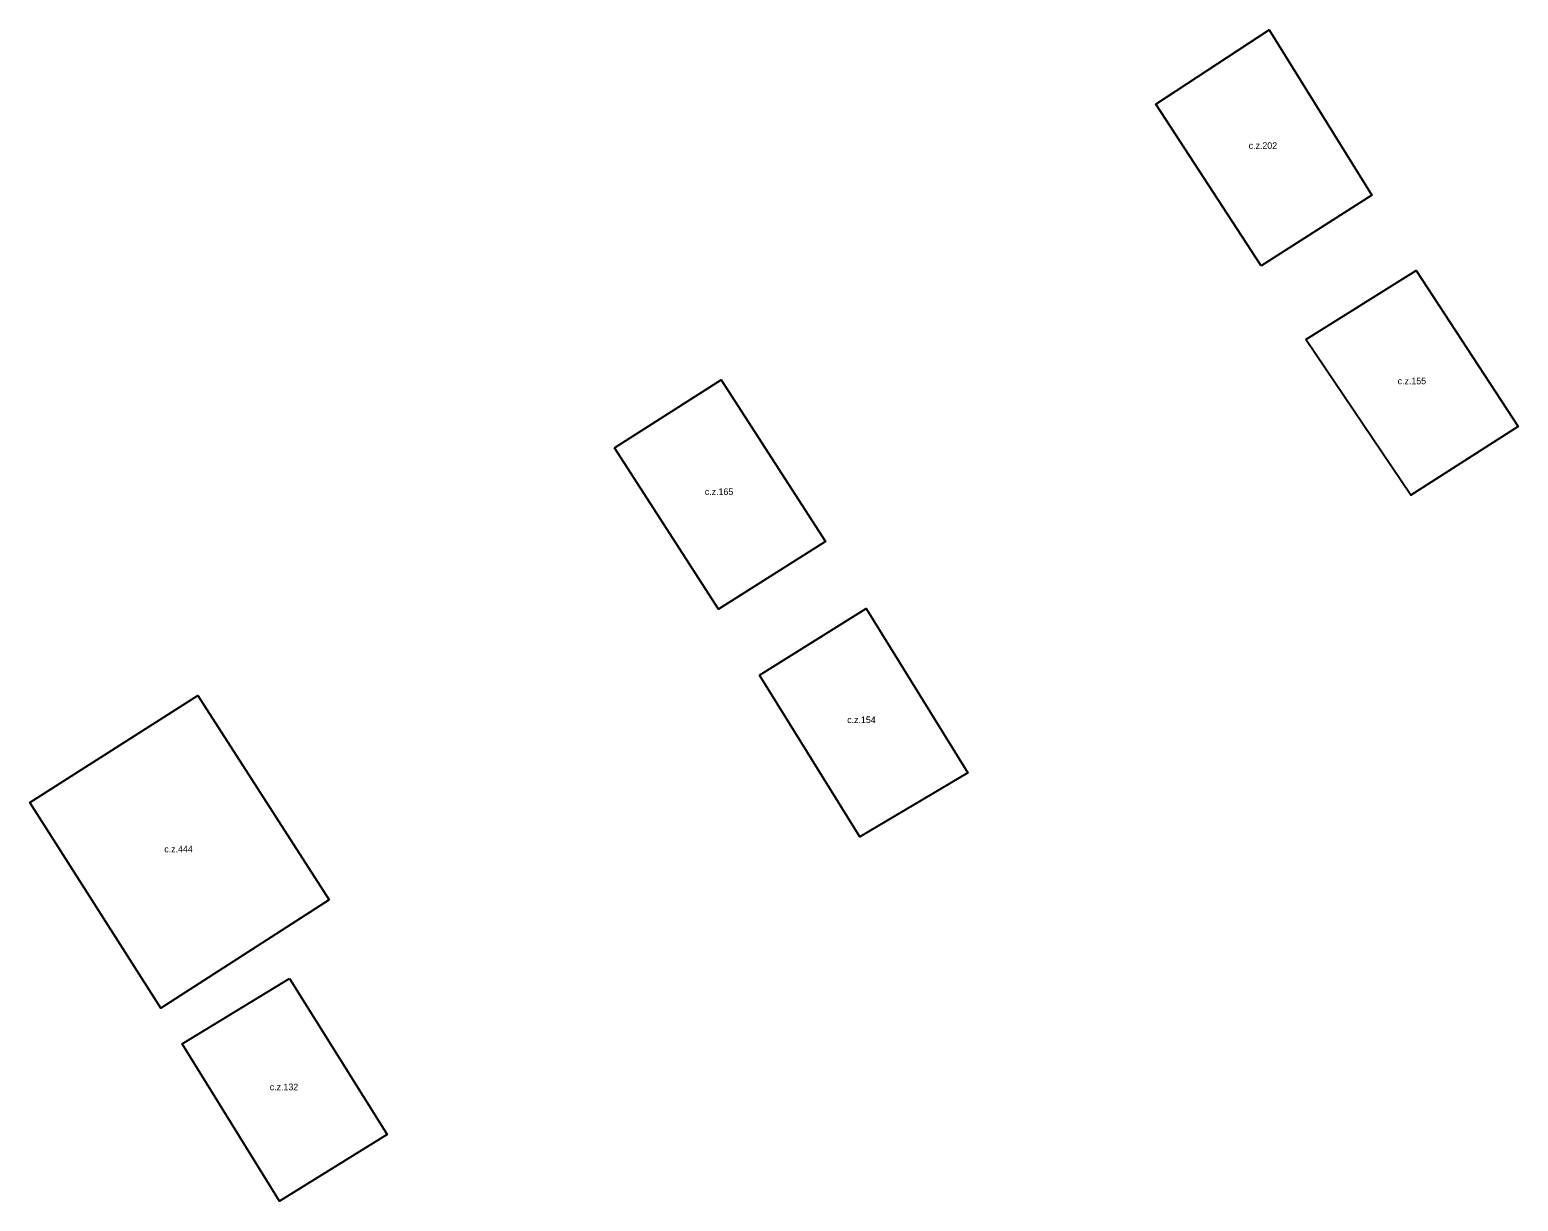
# Model space of a CAD drawing. Extents: x -600391 to -599491, y -1160176 to -1159402.
# Drawn here: x -599767.76 to -599745.18, y -1159453.12 to -1159435.35 of the extents above; entities that cross this region are included whole.
import ezdxf

# ---------------------------------------------------------------- set-up
doc = ezdxf.new("R2010")
doc.units = 0
for name, color, linetype in [('Level 24', 7, 'Continuous'), ('Level 61', 7, 'Continuous'), ('Level 62', 7, 'Continuous')]:
    doc.layers.add(name, color=color, linetype=linetype)

msp = doc.modelspace()

# ---------------------------------------------------------------- linework, layer by layer
at = {"layer": 'Level 61'}
for points in [[(-599750.68, -1159436.48), (-599748.96, -1159435.35)], [(-599748.96, -1159435.35), (-599747.4, -1159437.86)], [(-599749.08, -1159438.93), (-599750.68, -1159436.48)], [(-599747.4, -1159437.86), (-599749.08, -1159438.93)], [(-599748.4, -1159440.05), (-599746.73, -1159439)], [(-599746.73, -1159439), (-599745.18, -1159441.37)], [(-599746.81, -1159442.41), (-599748.4, -1159440.05)], [(-599758.89, -1159441.69), (-599757.27, -1159440.66)], [(-599757.27, -1159440.66), (-599755.69, -1159443.11)], [(-599745.18, -1159441.37), (-599746.81, -1159442.41)], [(-599757.31, -1159444.14), (-599758.89, -1159441.69)], [(-599755.69, -1159443.11), (-599757.31, -1159444.14)], [(-599756.69, -1159445.14), (-599755.07, -1159444.13)], [(-599755.07, -1159444.13), (-599753.53, -1159446.62)], [(-599755.17, -1159447.59), (-599756.69, -1159445.14)], [(-599767.76, -1159447.07), (-599765.21, -1159445.45)], [(-599765.21, -1159445.45), (-599763.22, -1159448.55)], [(-599753.53, -1159446.62), (-599755.17, -1159447.59)], [(-599765.77, -1159450.19), (-599767.76, -1159447.07)], [(-599763.22, -1159448.55), (-599765.77, -1159450.19)], [(-599765.45, -1159450.73), (-599763.82, -1159449.74)], [(-599763.82, -1159449.74), (-599762.34, -1159452.11)], [(-599763.97, -1159453.12), (-599765.45, -1159450.73)], [(-599762.34, -1159452.11), (-599763.97, -1159453.12)]]:
    msp.add_lwpolyline(points, dxfattribs=at)
at = {"layer": 'Level 62'}
for points in [[(-599749.08, -1159438.93), (-599750.68, -1159436.48), (-599748.96, -1159435.35), (-599747.4, -1159437.86), (-599749.08, -1159438.93)], [(-599748.4, -1159440.05), (-599746.73, -1159439), (-599745.18, -1159441.37), (-599746.81, -1159442.41), (-599748.4, -1159440.05)], [(-599758.89, -1159441.69), (-599757.27, -1159440.66), (-599755.69, -1159443.11), (-599757.31, -1159444.14), (-599758.89, -1159441.69)], [(-599756.69, -1159445.14), (-599755.07, -1159444.13), (-599753.53, -1159446.62), (-599755.17, -1159447.59), (-599756.69, -1159445.14)], [(-599763.22, -1159448.55), (-599765.77, -1159450.19), (-599767.76, -1159447.07), (-599765.21, -1159445.45), (-599763.22, -1159448.55)], [(-599763.82, -1159449.74), (-599762.34, -1159452.11), (-599763.97, -1159453.12), (-599765.45, -1159450.73), (-599763.82, -1159449.74)]]:
    msp.add_lwpolyline(points, dxfattribs=at)

# ---------------------------------------------------------------- texts
at = {"layer": 'Level 24'}
for s, p in [('c.z.202', (-599749.269, -1159437.157)), ('c.z.155', (-599747.009, -1159440.727)), ('c.z.165', (-599757.519, -1159442.407)), ('c.z.154', (-599755.359, -1159445.867)), ('c.z.444', (-599765.719, -1159447.827)), ('c.z.132', (-599764.119, -1159451.437))]:
    msp.add_text(s, height=0.1, dxfattribs=at).set_placement(p)

doc.saveas('drawing.dxf')
